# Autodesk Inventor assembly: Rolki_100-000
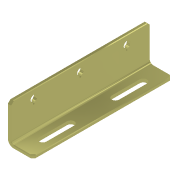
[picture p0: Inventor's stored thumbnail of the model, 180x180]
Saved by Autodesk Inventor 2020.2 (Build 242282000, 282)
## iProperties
Created: 2010-12
Part Number: Rolki_100-000
Document SubType Name: Assembly
Designer: F.Stasiak
Manager: www.cadconsulting.pl
Company: Fabian Stasiak CAD Consulting
Author: F.Stasiak
Subject: Zbiór ćwiczeń. Autodesk Inventor 2020. Kurs podstawowy
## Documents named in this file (2)
- C:\2020_Kurs_podstawowy\R6 Zespoły\iMate\Rolki_100-000.iam
- C:\2020_Kurs_podstawowy\R6 Zespoły\iMate\Szyna_100-100.ipt
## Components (1 placed, 1 different names)
1. Szyna_100-100:1
